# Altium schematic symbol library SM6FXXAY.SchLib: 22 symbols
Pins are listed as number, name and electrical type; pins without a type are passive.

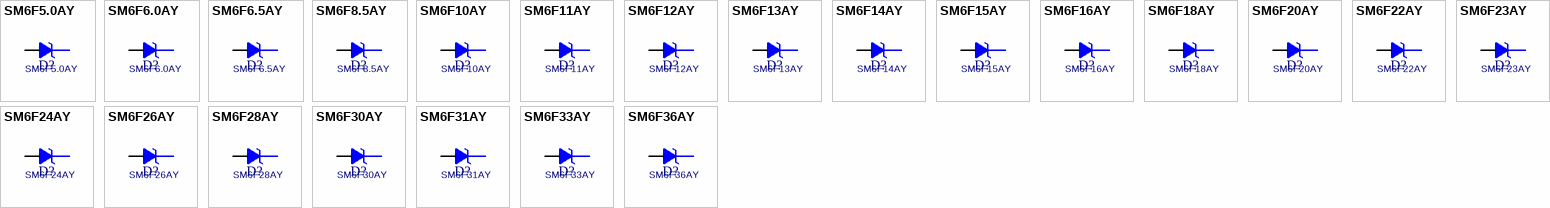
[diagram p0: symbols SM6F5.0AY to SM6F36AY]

## SM6F5.0AY
designator D?
footprint ST_SOD128FLAT
pins: 1 K, 2 A

## SM6F6.0AY
designator D?
footprint ST_SOD128FLAT
pins: 1 K, 2 A

## SM6F6.5AY
designator D?
footprint ST_SOD128FLAT
pins: 1 K, 2 A

## SM6F8.5AY
designator D?
footprint ST_SOD128FLAT
pins: 1 K, 2 A

## SM6F10AY
designator D?
footprint ST_SOD128FLAT
pins: 1 K, 2 A

## SM6F11AY
designator D?
footprint ST_SOD128FLAT
pins: 1 K, 2 A

## SM6F12AY
designator D?
footprint ST_SOD128FLAT
pins: 1 K, 2 A

## SM6F13AY
designator D?
footprint ST_SOD128FLAT
pins: 1 K, 2 A

## SM6F14AY
designator D?
footprint ST_SOD128FLAT
pins: 1 K, 2 A

## SM6F15AY
designator D?
footprint ST_SOD128FLAT
pins: 1 K, 2 A

## SM6F16AY
designator D?
footprint ST_SOD128FLAT
pins: 1 K, 2 A

## SM6F18AY
designator D?
footprint ST_SOD128FLAT
pins: 1 K, 2 A

## SM6F20AY
designator D?
footprint ST_SOD128FLAT
pins: 1 K, 2 A

## SM6F22AY
designator D?
footprint ST_SOD128FLAT
pins: 1 K, 2 A

## SM6F23AY
designator D?
footprint ST_SOD128FLAT
pins: 1 K, 2 A

## SM6F24AY
designator D?
footprint ST_SOD128FLAT
pins: 1 K, 2 A

## SM6F26AY
designator D?
footprint ST_SOD128FLAT
pins: 1 K, 2 A

## SM6F28AY
designator D?
footprint ST_SOD128FLAT
pins: 1 K, 2 A

## SM6F30AY
designator D?
footprint ST_SOD128FLAT
pins: 1 K, 2 A

## SM6F31AY
designator D?
footprint ST_SOD128FLAT
pins: 1 K, 2 A

## SM6F33AY
designator D?
footprint ST_SOD128FLAT
pins: 1 K, 2 A

## SM6F36AY
designator D?
footprint ST_SOD128FLAT
pins: 1 K, 2 A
